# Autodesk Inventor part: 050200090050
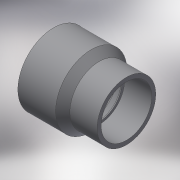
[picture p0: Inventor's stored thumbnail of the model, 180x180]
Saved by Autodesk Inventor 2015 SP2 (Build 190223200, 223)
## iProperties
Created: 2017-10
Part Number: 050200090050
Material: Generic
Description: PLASSON REDUCING SOCKET M.F.90(75)50 CEMENTED
Document SubType Name: Modeling
Designer: KIM
Density: 1 g/cm^3
Appearance: Default
Author: KIM
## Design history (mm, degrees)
derived "050200.ipt"
feature "Solid1::050200.ipt"
tag "TaggingFeature1"
body "Solid1"
other parameters: "d0" = 103, "d1" = 51, "d2" = 31, "d3" = 44, "d5" = 62, "d6" = 75, "d8" = 45, "d9" = 5.88003, "d12" = 0.75, "d_" = 75, "L_" = 51, "l_" = 44, "l_1" = 31, "E_" = 62, "H_" = 103, "d11" = 5.88003
